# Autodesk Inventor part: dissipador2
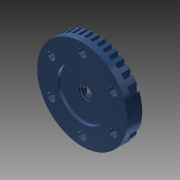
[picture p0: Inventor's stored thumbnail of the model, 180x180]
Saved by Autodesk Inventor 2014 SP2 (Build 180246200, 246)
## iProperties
Created: 2016-04
Part Number: dissipador2
Material: Genérico
Document SubType Name: Modeling
Designer: Celiberto
Density: 1 g/cm^3
Appearance: Acetinada manchada - Azul
Mass: 1.86414 g
Surface Area: 34.8535 cm^2
Volume: 1.86414 cm^3
Author: Celiberto
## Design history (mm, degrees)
sketch "Esboço1"
  geometry: C1 r 14.5 at (0, 0); 1 further point
  constraints: 1 centre point, 1 coincident
  dimensions: "d0" = 29 diameter of C1
extrude "Extrusão1" new body sketch "Esboço1" distance "d1" = 5; taper "d2" = 0 deg
sketch "Esboço2"
  geometry: C1 r 14.5 at (0, 0) reference; 1 further point
  dimensions: "d3" = 11.5 distance of C1.centre point (0, 11.5)
hole "Furo1" sketch "Esboço2" at (0, 11.5) diameter "d4" = 2.5; stored, may be unused: countersink angle "d8" = 90 deg, drill point angle "d10" = 118 deg; dims "d5" = 6, "d6" = 4, "d7" = 3, "d9" = 8
pattern_circular "Padrão circular1" dims angle "d12" = 360 deg
sketch "Esboço3"
  geometry: C1 r 14.5 at (0, 0) reference; C2 r 4 at (0, 0)
  constraints: 1 centre point, 1 coincident
  dimensions: "d14" = 8 diameter of C2
extrude "Extrusão2" cut sketch "Esboço3" distance "d15" = 3; taper "d16" = 0 deg
sketch "Esboço4"
  geometry: C1 r 14.5 at (0, 0) reference; C2 r 8 at (0, 0)
  constraints: 1 centre point, 1 coincident
  dimensions: "d17" = 16 diameter of C2
extrude "Extrusão3" cut sketch "Esboço4" distance "d18" = 1; taper "d19" = 0 deg
sketch "Esboço5"
  geometry: C1 r 8 at (0, 0) reference; 1 further point
  constraints: 1 coincident
hole "Furo2" sketch "Esboço5" at (0, 0) diameter "d20" = 4.134; stored, may be unused: countersink angle "d24" = 90 deg, drill point angle "d26" = 118 deg; dims "d21" = 6, "d22" = 4, "d23" = 3, "d25" = 8
chamfer "Chanfro1" distance "d39" = 0.2; stored, may be unused: second distance "d40" = 2, angle "d41" = 45 deg
chamfer "Chanfro2" distance "d42" = 0.2; stored, may be unused: second distance "d43" = 2, angle "d44" = 45 deg
sketch "Esboço7" dims "d56" = 10, "d60" = 10
  geometry: L1 (-0.164, -1.999)-(-0.055, -1.999); L2 (-0.5, 15.298)-(-1.5, 15.298); L3 (-1.5, 15.298)-(-1.5, -15.093); L4 (-1.5, -15.093)-(-0.5, -15.093); L5 (-0.5, -15.093)-(-0.5, 15.298); L6 (-0.5, 15.298)-(-1.5, -15.093); L7 (-1.5, 15.298)-(-0.5, -15.093); L8 (0, 0)-(0, 2.71); L9 (-3.5, 15.298)-(-3.5, -15.093); L10 (-2.5, 15.298)-(-3.5, 15.298); L11 (-2.5, -15.093)-(-2.5, 15.298); L12 (-5.5, 15.298)-(-5.5, -15.093); L13 (-4.5, 15.298)-(-5.5, 15.298); L14 (-4.5, -15.093)-(-4.5, 15.298); L15 (-7.5, 15.298)-(-7.5, -15.093); L16 (-6.5, 15.298)-(-7.5, 15.298); L17 (-6.5, -15.093)-(-6.5, 15.298); L18 (-9.5, 15.298)-(-9.5, -15.093); L19 (-8.5, 15.298)-(-9.5, 15.298); L20 (-8.5, -15.093)-(-8.5, 15.298); L21 (-11.5, 15.298)-(-11.5, -15.093); L22 (-10.5, 15.298)-(-11.5, 15.298); L23 (-10.5, -15.093)-(-10.5, 15.298); L24 (-13.5, 15.298)-(-13.5, -15.093); L25 (-12.5, 15.298)-(-13.5, 15.298); L26 (-12.5, -15.093)-(-12.5, 15.298); L27 (1.5, 15.298)-(0.5, 15.298); L28 (0.5, 15.298)-(0.5, -15.093); L29 (1.5, -15.093)-(1.5, 15.298); L30 (0.5, -15.093)-(1.5, -15.093); L31 (3.5, 15.298)-(2.5, 15.298); L32 (2.5, 15.298)-(2.5, -15.093); L33 (3.5, -15.093)-(3.5, 15.298); L34 (2.5, -15.093)-(3.5, -15.093); L35 (5.5, 15.298)-(4.5, 15.298); L36 (4.5, 15.298)-(4.5, -15.093); L37 (5.5, -15.093)-(5.5, 15.298); L38 (4.5, -15.093)-(5.5, -15.093); L39 (7.5, 15.298)-(6.5, 15.298); L40 (6.5, 15.298)-(6.5, -15.093); L41 (7.5, -15.093)-(7.5, 15.298); L42 (6.5, -15.093)-(7.5, -15.093); L43 (9.5, 15.298)-(8.5, 15.298); L44 (8.5, 15.298)-(8.5, -15.093); L45 (9.5, -15.093)-(9.5, 15.298); L46 (8.5, -15.093)-(9.5, -15.093); L47 (11.5, 15.298)-(10.5, 15.298); L48 (10.5, 15.298)-(10.5, -15.093); L49 (11.5, -15.093)-(11.5, 15.298); L50 (10.5, -15.093)-(11.5, -15.093); L51 (13.5, 15.298)-(12.5, 15.298); L52 (12.5, 15.298)-(12.5, -15.093); L53 (13.5, -15.093)-(13.5, 15.298); L54 (12.5, -15.093)-(13.5, -15.093); L55 (-2.5, -15.093)-(-3.5, -15.093); L56 (-4.5, -15.093)-(-5.5, -15.093); L57 (-6.5, -15.093)-(-7.5, -15.093); L58 (-8.5, -15.093)-(-9.5, -15.093); L59 (-10.5, -15.093)-(-11.5, -15.093); L60 (-12.5, -15.093)-(-13.5, -15.093); C1 r 14.3 at (0, 0) reference; 3 further points
  constraints: 120 end point, 8 collinear, 3 horizontal, 3 parallel, 2 midpoint, 1 perpendicular, 98 other
  dimensions: "d49" = 0.5 distance between parallel lines of L5 L8; "d50" = 1 distance of L2.start L2.end; "d53" = 2 distance of L2.end L9.start; "d63" = 2 distance of L2.start L27.start
extrude "Extrusão4" cut sketch "Esboço7" distance "d65" = 3; taper "d66" = 0 deg
node "Sólido1"
